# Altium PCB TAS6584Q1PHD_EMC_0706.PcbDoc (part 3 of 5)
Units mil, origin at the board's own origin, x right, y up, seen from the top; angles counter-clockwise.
Board outline 7086.61 x 5118.11 mil, 6 copper layers (Top Layer, GND02, SIG03, SIG04, GND05, Bottom Layer), stack 60.484 mil thick; 461 components, 247 nets, 1337 pads, 1658 vias.
Unrouted connection lines stored in the file: 67.
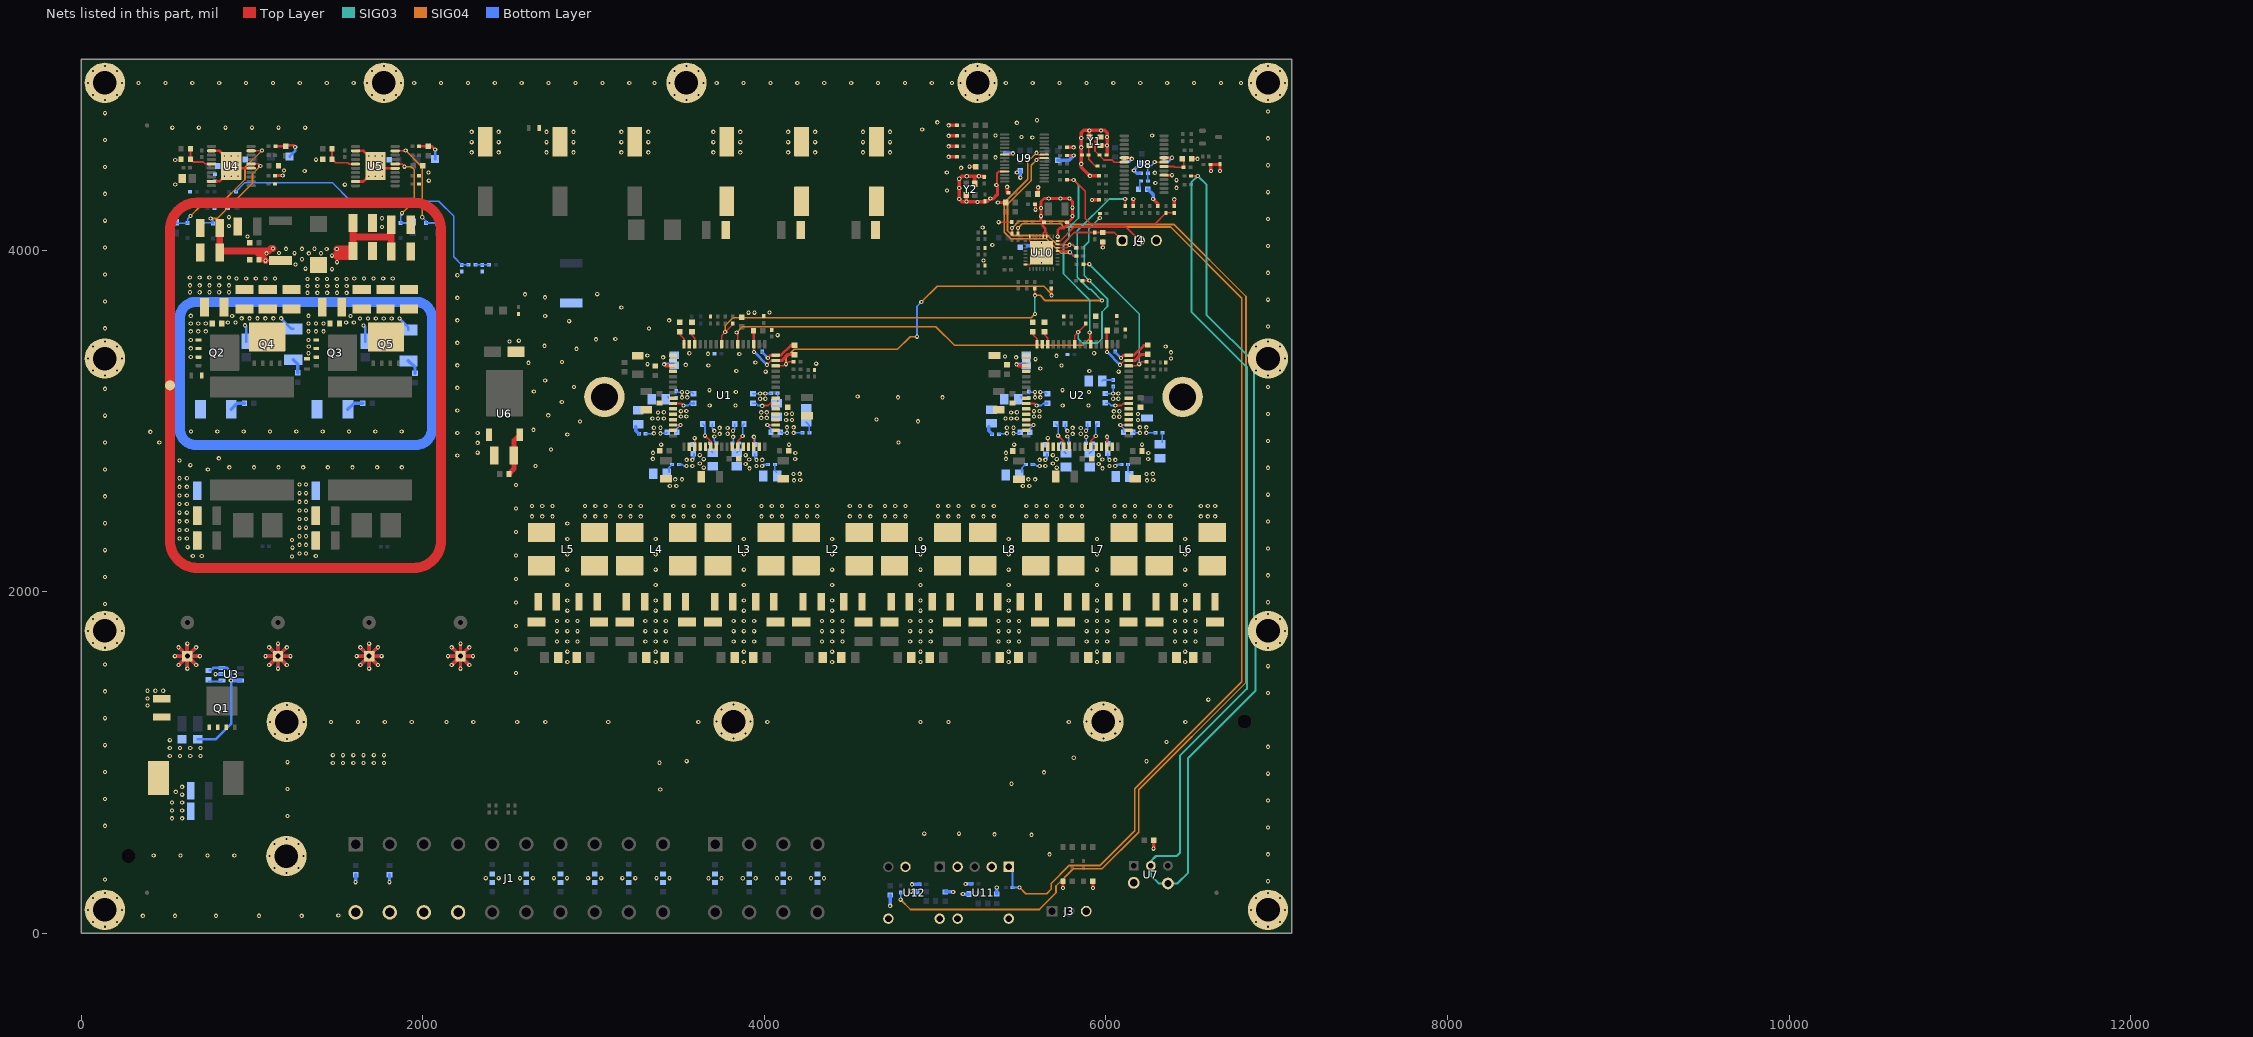
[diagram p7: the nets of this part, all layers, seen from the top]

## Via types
v1: diameter 25, hole 12, Top Layer to Bottom Layer, 1387 vias
v2: diameter 25, hole 12, Top Layer to Bottom Layer, tented both sides, 242 vias
v3: diameter 19.68, hole 7.87, Top Layer to Bottom Layer, 29 vias

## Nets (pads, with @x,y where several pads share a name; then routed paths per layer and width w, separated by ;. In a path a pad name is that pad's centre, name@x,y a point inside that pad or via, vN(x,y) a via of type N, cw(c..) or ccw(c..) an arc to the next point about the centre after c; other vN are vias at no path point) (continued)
GND: C1.2 C2.2 C3.2 C4.2 C5.2 C6.2 C7.2 C8.2 C9.2 C10.1 C11.1 C12.2 C15.2 C16.2 C17.2 C18.2 C35.2 C36.2 C37.2 C38.2 C39.2 C40.2 C41.2 C42.2 C43.2 C44.2 C45.2 C46.2 C47.2 C48.2 C49.2 C50.2 C51.2 C52.2 C53.2 C54.2 C55.2 C56.2 C57.2 C58.2 C59.2 C60.2 C61.2 C62.2 C63.2 C64.2 C65.2 C66.2 C67.2 C68.1 C69.1 C70.2 C73.2 C74.2 C75.2 C76.2 C93.2 C94.2 C95.2 C96.2 C97.2 C98.2 C99.2 C100.2 C101.2 C102.2 C103.2 C104.2 C105.2 C106.2 C107.2 C108.2 C109.2 C110.2 C111.2 C112.2 C113.2 C114.2 C115.2 C116.2 C117.2 C119.2 C121.2 C122.2 C123.2 C124.2 C125.1 C126.2 C128.2 C129.1 C131.1 C133.1 C134.2 C135.1 C136.1 C137.2 C138.2 C139.2 C140.2 C141.2 C143.2 C145.2 C146.2 C147.2 C148.2 C149.2 C150.2 C151.2 C152.2 C153.2 C158.2 C159.2 C160.2 C161.2 C162.2 C163.2 C164.2 C165.2 C166.2 C167.2 C168.2 C169.1 C170.1 C171.1 C172.1 C173.1 C174.1 C175.1 C176.2 C177.2 C178.2 C179.1 C180.2 C181.2 C182.1 C183.2 C184.2 C185.2 C186.2 C187.2 C188.2 C189.2 C190.2 C191.2 C192.2 C193.2 C194.2 C199.1 C200.1 C201.1 C202.2 C203.2 C204.2 C205.1 C206.2 C207.1 C208.2 C209.1 C210.2 C211.2 C212.1 C213.1 C214.2 C215.2 C216.1 C217.1 C218.2 C219.2 C220.2 C221.2 C222.2 C223.2 C224.2 C225.2 C226.2 C227.2 C228.1 C229.1 C230.1 D13.2 H1.1 H1.2 J1.2 J1.4 J1.6 J1.8 J3.3 J4.3 MP1.1 MP2.1 pad.2 pad.3 pad.6@620.79,1623.36 pad.6@1151.41,1623.36 pad.6@1685.2,1623.36 pad.6@2220.3,1623.36 Q2.1 Q2.2 Q2.3 Q3.1 Q3.2 Q3.3 R9.2 R11.2 R13.1 R14.2 R15.2 R16.2 R17.2 R18.2 R19.2 R20.2 R21.2 R22.2 R23.2 R34.2 R38.2 R40.2 R42.1 R43.2 R44.2 R45.2 R46.2 R47.2 R48.2 R49.2 R50.2 R51.2 R63.1 R67.1 R70.1 R73.1 R74.1 R80.1 R82.1 R86.1 R93.1 R94.1 R102.2 R108.2 R109.2 R124.2 R127.1 R132.1 R133.1 R134.1 R135.1 R136.1 R137.1 R156.1 RT1.1 RT2.1 RT3.1 U1.15 U1.17 U1.18 U1.20 U1.27 U1.28 U1.29 U1.36 U1.37 U1.44 U1.45 U1.52 U1.53 U1.54 U2.15 U2.17 U2.18 U2.20 U2.27 U2.28 U2.29 U2.36 U2.37 U2.44 U2.45 U2.52 U2.53 U2.54 U3.2 U4.2 U4.9 U4.15 U4.21 U5.2 U5.9 U5.15 U5.21 U6.1 U7.2 U7.4 U7.5 U8.6 U8.19 U8.23 U9.7 U9.12 U10.8 U10.27 U10.28 U10.32 U10.33 U11.2 U11.4 U11.5 U11.8 U12.3 U12.5 U12.8 Y1.2 Y1.4 Y2.2 Y2.4 | length 19128.9
  Top Layer w10: v1(5371.59,4165) D13.2@5449.15,4165 ; U10.8@5528.22,3916.85 5553.81,3916.85 v3(5622.71,3985.75) 5553.81,4054.65 U10.32@5553.81,4080.24 ; U10.28@5632.55,4080.24 5632.55,4100.55 5644,4112 5652.24,4103.76 U10.27@5652.24,4080.24
  Top Layer w11: 5371.62,4461.26 U9.12@5406.61,4461.26 ; U9.7@5406.61,4559.69 5446.69,4559.69 v1(5455,4568)
  Top Layer w12: v1(5358,4382) 5362.36,4386.36 5362.36,4452 5371.62,4461.26 ; Y1.2@5967.48,4613.89 v1(6006.49,4613.89) ; C178.2@6502.24,4435.2 v1(6537.59,4435.2)
  Top Layer w16: U4.9@761.89,4403.81 808.15,4403.81 v3(838.66,4434.33) ; U4.2@761.89,4582.95 808.15,4582.95 v3(838.66,4552.44) ; v3(917.4,4473.7) 924.29,4480.59 U4.15@994.17,4480.59 ; R67.1@1134.49,4437.38 1134.62,4437.51 1178.47,4437.51 v1(1178.6,4437.64) ; U5.9@1605.51,4403.42 1651.77,4403.42 v3(1682.28,4433.93) ; U5.2@1605.51,4582.55 1651.77,4582.55 v3(1682.28,4552.04) ; v3(1761.02,4473.3) 1767.91,4480.19 U5.15@1837.8,4480.19 ; v1(5201.2,4490) C203.2@5237.44,4490 ; 5644,4112 5644,4127.73 5630.31,4141.42 5630.31,4165 5620,4175.31 v1(5620,4200) v1(5620,4247.91) 5620,4286 5637,4303 v1(5665,4303) v1(5734,4303) v1(5787,4303) 5804,4286 v1(5804,4249.5) v1(5804,4201) 5804,4189.04 5779.96,4165 5779.96,4155.96 5754.5,4130.5 5731.62,4130.5 5717,4115.88 v1(5717,4080) ; v1(5748.38,265.73) C189.2@5748.38,305.75 ; v1(5923.62,265.04) C187.2@5923.62,305.05 ; U8.6@6107.72,4541.97 6145.17,4541.97 v1(6151.55,4535.59) ; U8.19@6340,4439.61 v1(6387.03,4439.61) ; U8.23@6340,4541.97 v1(6387.03,4541.97) ; C181.2@6502.24,4535.59 v1(6536.59,4535.59)
  Top Layer w20: v1(547.64,1623.36) pad.6@620.79,1623.36 ; v1(569.07,1571.64) pad.6@620.79,1623.36 ; v1(569.07,1675.09) pad.6@620.79,1623.36 ; v1(620.79,1550.22) pad.6@620.79,1623.36 ; v1(620.79,1696.51) pad.6@620.79,1623.36 ; v1(672.52,1571.64) pad.6@620.79,1623.36 ; v1(672.52,1675.09) pad.6@620.79,1623.36 ; v1(693.94,1623.36) pad.6@620.79,1623.36 ; v1(1078.26,1623.36) pad.6@1151.41,1623.36 ; v1(1099.68,1571.64) pad.6@1151.41,1623.36 ; v1(1099.68,1675.09) pad.6@1151.41,1623.36 ; v1(1151.41,1550.22) pad.6@1151.41,1623.36 ; v1(1151.41,1696.51) pad.6@1151.41,1623.36 ; v1(1203.13,1571.64) pad.6@1151.41,1623.36 ; v1(1203.13,1675.09) pad.6@1151.41,1623.36 ; v1(1224.56,1623.36) pad.6@1151.41,1623.36 ; v1(1612.05,1623.36) pad.6@1685.2,1623.36 ; v1(1633.47,1571.64) pad.6@1685.2,1623.36 ; v1(1633.47,1675.09) pad.6@1685.2,1623.36 ; v1(1685.2,1550.22) pad.6@1685.2,1623.36 ; v1(1685.2,1696.51) pad.6@1685.2,1623.36 ; v1(1736.92,1571.64) pad.6@1685.2,1623.36 ; v1(1736.92,1675.09) pad.6@1685.2,1623.36 ; v1(1758.34,1623.36) pad.6@1685.2,1623.36 ; v1(2147.15,1623.36) pad.6@2220.3,1623.36 ; v1(2168.57,1571.64) pad.6@2220.3,1623.36 ; v1(2168.57,1675.09) pad.6@2220.3,1623.36 ; v1(2220.3,1550.22) pad.6@2220.3,1623.36 ; v1(2220.3,1696.51) pad.6@2220.3,1623.36 ; v1(2272.02,1571.64) pad.6@2220.3,1623.36 ; v1(2272.02,1675.09) pad.6@2220.3,1623.36 ; v1(2293.45,1623.36) pad.6@2220.3,1623.36 ; v1(5079.07,4547.07) R133.1@5126.67,4547.07 ; v1(5079.07,4608.53) R135.1@5126.67,4608.53 ; v1(5079.07,4670) R134.1@5126.67,4670 ; v1(5079.07,4731.47) R132.1@5126.67,4731.47 ; Y2.2@5182.95,4324.72 v1(5182.95,4285.05) ; Y2.4@5232.16,4389.68 5232.16,4432.75 5233,4433.59 ; C199.1@5291.78,4433.59 v1(5255.59,4433.59) 5233,4433.59 ; v1(5358,4382) 5364.84,4375.16 5364.84,4328.12 5339.56,4302.85 v1(5322.85,4302.85) 5307.28,4287.28 C200.1@5291.78,4287.28 5287.84,4283.35 v1(5248.35,4283.35) 5184.65,4283.35 v1(5182.95,4285.05) ; v1(5367,4280) C204.2@5405.9,4280 ; C205.1@5421.65,4337.09 v1(5421.65,4371.65) ; v1(5587.24,4237.76) C201.1@5587.24,4270 ; C202.2@5602.99,4330 v1(5602.99,4368.99) ; R136.1@5774.64,4555.24 v1(5811,4555.24) ; R137.1@5774.64,4602.95 v1(5811,4602.95) ; Y1.4@5902.52,4663.11 v1(5902.52,4702) ; v1(5918,4295) R109.2@5956.38,4295 ; R108.2@5956.38,4436.19 v1(5905.42,4436.19) 5855.28,4486.33 v1(5855.28,4506.33) v1(5855.28,4603) v1(5855.28,4658) 5855.28,4687.28 5870,4702 v1(5902.52,4702) ; v1(5981.55,4016.33) C218.2@5981.55,4056.76 ; C177.2@6006.49,4558 v1(6006.49,4613.89) v1(6006.49,4663.09) 6006.49,4688.01 5992.5,4702 v1(5971,4702) v1(5902.52,4702) ; C188.2@6160.51,4262.4 v1(6160.51,4300.49) ; v1(6276.73,4300) 6304.08,4272.64 C185.2@6304.08,4262.4 ; v1(6279.02,496.1) C175.1@6279.02,545 ; C186.2@6399.8,4262.4 v1(6399.8,4298.55) ; v1(6614.74,4464) 6614.74,4502.45 6668,4502.45 v1(6668,4464) ; v1(5182.95,4285.05) 5155.95,4285.05 v1(5141,4300) v1(5141,4365) v1(5141,4419) 5155.59,4433.59 v1(5184.65,4433.59) 5233,4433.59
  SIG03 w12: v1@6876,1700.89 6876,1421.91 6481,1026.91 6481,354.42 6418.9,292.31 U7.5@6362.9,292.31 6308.28,292.31 6262.9,337.69 U7.2@6262.9,395.86 6262.9,422.9 6292.8,452.8 6415.02,452.8 6432.63,470.41 6432.63,1039.63 6824.98,1431.98 6824.98,3315.02 6500,3640 6500,4397.61 v1(6537.59,4435.2) 6590,4382.78 6590,3620.49 6876,3334.49 v1@6876,3296.07 ; v1(6878.74,1700.89) 6866.83,1712.8 6866.83,1829.13 v1(6878.74,1841.04) 6866.91,1852.88 6866.91,3284.23 v1(6878.74,3296.07)
  Bottom Layer w16: v1(785.18,1517.81) U3.2@823.3,1517.81 ; C182.1@6107.72,4520.31 6136.27,4520.31 v1(6151.55,4535.59) ; C179.1@6340,4520.31 6365.38,4520.31 v1(6387.03,4541.97)
  Bottom Layer w20: v1(547.64,1623.36) pad.6@620.79,1623.36 ; v1(569.07,1571.64) pad.6@620.79,1623.36 ; v1(569.07,1675.09) pad.6@620.79,1623.36 ; v1(620.79,1550.22) pad.6@620.79,1623.36 ; v1(620.79,1696.51) pad.6@620.79,1623.36 ; v1(672.52,1571.64) pad.6@620.79,1623.36 ; v1(672.52,1675.09) pad.6@620.79,1623.36 ; v1(693.94,1623.36) pad.6@620.79,1623.36 ; v1(1078.26,1623.36) pad.6@1151.41,1623.36 ; v1(1099.68,1571.64) pad.6@1151.41,1623.36 ; v1(1099.68,1675.09) pad.6@1151.41,1623.36 ; v1(1151.41,1550.22) pad.6@1151.41,1623.36 ; v1(1151.41,1696.51) pad.6@1151.41,1623.36 ; v1(1203.13,1571.64) pad.6@1151.41,1623.36 ; v1(1203.13,1675.09) pad.6@1151.41,1623.36 ; v1(1224.56,1623.36) pad.6@1151.41,1623.36 ; v1(1606,299.56) C121.2@1606,342.44 ; v1(1612.05,1623.36) pad.6@1685.2,1623.36 ; v1(1633.47,1571.64) pad.6@1685.2,1623.36 ; v1(1633.47,1675.09) pad.6@1685.2,1623.36 ; v1(1685.2,1550.22) pad.6@1685.2,1623.36 ; v1(1685.2,1696.51) pad.6@1685.2,1623.36 ; v1(1736.92,1571.64) pad.6@1685.2,1623.36 ; v1(1736.92,1675.09) pad.6@1685.2,1623.36 ; v1(1758.34,1623.36) pad.6@1685.2,1623.36 ; v1(1804.28,299.56) C122.2@1804.28,342.44 ; v1(2147.15,1623.36) pad.6@2220.3,1623.36 ; v1(2168.57,1571.64) pad.6@2220.3,1623.36 ; v1(2168.57,1675.09) pad.6@2220.3,1623.36 ; v1(2220.3,1550.22) pad.6@2220.3,1623.36 ; v1(2220.3,1696.51) pad.6@2220.3,1623.36 ; v1(2272.02,1571.64) pad.6@2220.3,1623.36 ; v1(2272.02,1675.09) pad.6@2220.3,1623.36 ; v1(2293.45,1623.36) pad.6@2220.3,1623.36 ; v1(4736.22,161.36) R156.1@4736.22,224.53 ; v1(4858.4,244.19) C211.2@4892.45,244.19 ; v1(4864.01,287.19) C213.1@4908.19,287.19 ; C215.2@5059.2,242.56 v1(5105.37,242.56) ; v1(5161.72,230) C210.2@5197.61,230 ; v1(5178.71,289.5) C212.1@5213.36,289.5 ; C214.2@5360.46,230.35 v1(5360.46,268.29) ; C207.1@5406.61,4567.56 5454.56,4567.56 v1(5455,4568) ; v1(5498.58,4425.46) C206.2@5498.58,4466.67 ; 5539.13,4025.71 5604.6,4025.71 v3(5622.71,4043.82) ; C194.2@5717,4527.68 5717.12,4527.8 5783.56,4527.8 v1(5811,4555.24) ; C183.2@6198.27,4451.42 6179.55,4451.42 v1(6163.15,4467.81) 6201.28,4505.94 C176.2@6210,4505.94 ; C184.2@6245.51,4358.01 6276.73,4326.8 v1(6276.73,4300)
  other v1: 137.8,38.69 6948.82,38.69 67.72,67.72 207.87,67.72 6878.74,67.72 7018.89,67.72 360,102.9 548.96,102.9 787.92,102.9 1040.93,102.9 1290.01,102.9 1505,105 38.69,137.8 236.9,137.8 6849.72,137.8 7047.92,137.8 67.72,207.87 207.87,207.87 6878.74,207.87 7018.89,207.87 137.8,236.9 6948.82,236.9 2368,323 2444,323 2568,323 2644,323 2768,323 2844,323 2968,323 3044,323 3168,323 3244,323 3368,323 3444,323 3673,322.65 3749,322.65 3873,322.65 3949,322.65 4073,322.65 4149,322.65 4273,322.65 4349,322.65 1200.79,353.65 1130.71,382.68 1270.86,382.68 1101.69,452.76 1299.89,452.76 1130.71,522.83 1270.86,522.83 1200.79,551.86 5563.41,576.91 5347.67,579.8 4935.9,584.1 5138.91,584.1 530.47,673.87 590.47,673.87 530.47,720 590.47,720 530.47,766.13 590.47,766.13 590.47,812.4 552.85,828.7 3389.86,842.3 590.47,858.02 5446.16,876.01 5636.56,943.17 1472.76,997.56 1532.76,997.56 1592.76,997.56 1652.76,997.56 1712.76,997.56 1772.76,997.56 3386,999 6238,1008.02 3544.96,1008.33 5811.32,1028.38 1472.76,1043.69 1532.76,1043.69 1592.76,1043.69 1652.76,1043.69 1712.76,1043.69 1772.76,1043.69 6355.14,1120 1203.18,1138.67 3818.9,1140.9 5984.25,1141.06 1133.1,1167.69 1273.25,1167.69 3748.82,1169.92 3888.97,1169.92 5914.18,1170.08 6054.33,1170.08 3085.44,1237.12 3612.71,1237.12 4016.98,1237.12 4913.94,1237.12 5077.78,1237.12 5782.49,1237.12 6464.52,1237.12 1104.07,1237.77 1302.28,1237.77 2717.04,1237.77 3719.8,1240 3918,1240 5885.15,1240.16 6083.35,1240.16 1133.1,1307.85 1273.25,1307.85 3748.82,1310.08 3888.97,1310.08 5914.18,1310.23 6054.33,1310.23 388,1335 1203.18,1336.87 3818.9,1339.1 5984.25,1339.26 388,1375 386.76,1420.82 432.9,1420.82 479.03,1420.82 2545.31,1524.09 2845.97,1589.59 3362.83,1589.59 3879.69,1589.59 4396.55,1589.59 4913.42,1589.59 5430.28,1589.59 5947.14,1589.59 6464,1589.59 2845.97,1649.59 3362.83,1649.59 3879.69,1649.59 4396.55,1649.59 4913.42,1649.59 5430.28,1649.59 5947.14,1649.59 6464,1649.59 2545.31,1661.86 6948.82,1671.87 137.8,1672.55 7018.89,1700.89 67.72,1701.58 207.87,1701.58 2785.97,1709.59 2845.97,1709.59 2905.97,1709.59 3302.83,1709.59 3362.83,1709.59 3422.83,1709.59 3819.69,1709.59 3879.69,1709.59 3939.69,1709.59 4336.55,1709.59 4396.55,1709.59 4456.55,1709.59 4853.42,1709.59 4913.42,1709.59 4973.42,1709.59 5370.28,1709.59 5430.28,1709.59 5490.28,1709.59 5887.14,1709.59 5947.14,1709.59 6007.14,1709.59 6404,1709.59 6464,1709.59 6524,1709.59 2785.97,1769.59 2845.97,1769.59 2905.97,1769.59 3302.83,1769.59 3362.83,1769.59 3422.83,1769.59 3819.69,1769.59 3879.69,1769.59 3939.69,1769.59 4336.55,1769.59 4396.55,1769.59 4456.55,1769.59 4853.42,1769.59 4913.42,1769.59 4973.42,1769.59 5370.28,1769.59 5430.28,1769.59 5490.28,1769.59 5887.14,1769.59 5947.14,1769.59 6007.14,1769.59 6404,1769.59 6464,1769.59 6524,1769.59 7047.92,1770.97 38.69,1771.65 236.9,1771.65 2545.31,1799.63 2785.97,1829.59 2845.97,1829.59 2905.97,1829.59 3302.83,1829.59 3362.83,1829.59 3422.83,1829.59 3819.69,1829.59 3879.69,1829.59 3939.69,1829.59 4336.55,1829.59 4396.55,1829.59 4456.55,1829.59 4853.42,1829.59 4913.42,1829.59 4973.42,1829.59 5370.28,1829.59 5430.28,1829.59 5490.28,1829.59 5887.14,1829.59 5947.14,1829.59 6007.14,1829.59 6404,1829.59 6464,1829.59 6524,1829.59 7018.89,1841.04 67.72,1841.73 207.87,1841.73 6948.82,1870.07 137.8,1870.76 2845.97,1889.59 3362.83,1889.59 3879.69,1889.59 4396.55,1889.59 4913.42,1889.59 5430.28,1889.59 5947.14,1889.59 6464,1889.59 2545.31,1937.4 2845.97,1949.59 3362.83,1949.59 3879.69,1949.59 4396.55,1949.59 4913.42,1949.59 5430.28,1949.59 5947.14,1949.59 6464,1949.59 2845.97,2039.59 3362.83,2039.59 3879.69,2039.59 4396.55,2039.59 4913.42,2039.59 5430.28,2039.59 5947.14,2039.59 6464,2039.59 2545.31,2075.17 2845.97,2129.59 3362.83,2129.59 3879.69,2129.59 4396.55,2129.59 4913.42,2129.59 5430.28,2129.59 5947.14,2129.59 6464,2129.59 1233.88,2206.7 652.99,2209.67 704.9,2209.67 1372.91,2209.67 2545.31,2212.94 2845.97,2219.59 3362.83,2219.59 3879.69,2219.59 4396.55,2219.59 4913.42,2219.59 5430.28,2219.59 5947.14,2219.59 6464,2219.59 1277.62,2225 1315,2225 1236.78,2258.35 622.63,2261.53 1277.62,2275 1315,2275 1233.21,2303.19 2845.97,2309.59 3362.83,2309.59 3879.69,2309.59 4396.55,2309.59 4913.42,2309.59 5430.28,2309.59 5947.14,2309.59 6464,2309.59 575.25,2311.97 617.63,2311.97 1277.62,2325.43 1315,2325.43 2545.31,2350.71 575.25,2362.4 617.63,2362.4 1277.62,2375.87 1315,2375.87 2845.97,2399.59 575.25,2412.83 617.63,2412.83 1277.62,2426.3 1315,2426.3 575.25,2463.27 617.63,2463.27 1277.62,2476.73 1315,2476.73 2545.31,2488.47 575.25,2513.7 617.63,2513.7 1277.62,2527.17 1315,2527.17 575.25,2564.13 617.63,2564.13 1277.62,2577.6 1315,2577.6 575.25,2614.57 617.63,2614.57 2545.31,2626.24 1277.62,2628.03 1315,2628.03 575.25,2665 617.63,2665 740.57,2716.54 866.26,2729.16 1010.58,2729.16 1154.91,2729.16 1299.24,2729.16 1443.56,2729.16 1587.89,2729.16 1732.21,2729.16 1876.54,2729.16 2660.05,2736.5 638,2742 575.25,2769.42 804.84,2781.66 2201.82,2798.66 2320.63,2814.97 2750.64,2833.4 2320.55,2872.72 456.3,2874.02 4785.18,2874.63 2846,2921.73 2320.55,2929.92 2201.82,2930.54 404,2937.1 642,2939 796.18,2939 950.37,2939 1104.55,2939 1258.74,2939 1412.92,2939 1567.11,2939 1721.29,2939 1875.48,2939 2647.63,2948.41 5419.46,2960.8 4171.27,2963.48 2919.54,2997.36 4899.93,2998.57 4656.25,3009.13 2734.15,3033.4 2201.82,3062.43 3679.09,3090.98 3830.74,3090.98 5746.45,3090.98 5898.09,3090.98 2813.4,3111.05 4782.43,3138.8 5043.22,3138.8 4546.06,3143.27 3832.82,3169.8 5900.18,3169.8 2649.46,3172.45 3678.39,3180.95 5745.74,3180.95 2201.82,3194.31 2884.28,3199.22 2715.98,3237 137.8,3267.04 6948.82,3267.04 3835.21,3292.75 5902.57,3292.75 67.72,3296.07 207.87,3296.07 7018.89,3296.07 5615.33,3308.26 3671.65,3324.98 5739,3324.98 2201.82,3326.19 3539.2,3329.46 3315.67,3333.22 4303.29,3336.05 2619.04,3341.14 3946.99,3342.9 2815.21,3345.97 5587.44,3362.37 38.69,3366.14 236.9,3366.14 6380.98,3366.89 7047.92,3366.14 3406.8,3373.43 5474.15,3373.43 640.71,3375.74 5408.73,3377.9 5710.59,3381.91 3314.55,3383.86 3852.84,3392.47 3670.17,3393.71 1330.61,3397.01 5931.17,3396.98 3560.41,3397.15 6380.98,3402.71 2899.91,3422.89 640.71,3425.63 67.72,3436.22 207.87,3436.22 6349.76,3436.22 6878.74,3436.22 7018.89,3436.22 1331.52,3437.29 2712.34,3440.35 2201.82,3458.07 137.8,3465.24 2506.97,3466.07 6948.82,3465.24 2561.73,3471.06 640.71,3475.14 1330.66,3475.14 3013.32,3478.42 3126.88,3480.54 4077.79,3503.04 640.71,3525.31 684.56,3525.31 728.4,3525.31 1330.66,3525.31 1374.5,3525.31 1418.35,3525.31 3324.13,3541.69 640.71,3571.29 684.56,3571.29 728.4,3571.29 1330.66,3571.29 1374.5,3571.29 1418.35,3571.29 2856.71,3584.86 2201.82,3589.96 3442.17,3589.67 2715.98,3614.74 640.71,3616.13 1330.66,3616.13 3906.38,3634.91 3941.9,3634.64 4029.82,3635.62 3162.2,3664.53 2201.82,3721.84 2714.53,3724.4 2597.84,3741.82 3020.96,3743.09 1324.94,3751.17 1382.08,3751.17 1439.23,3751.17 1496.37,3751.17 1553.52,3751.17 635.85,3754.17 692.99,3754.17 750.14,3754.17 807.28,3754.17 864.43,3754.17 1324.94,3790.91 1382.08,3790.91 1439.23,3790.91 1496.37,3790.91 1553.52,3790.91 635.85,3794.91 692.99,3794.91 750.14,3794.91 807.28,3794.91 864.43,3794.91 1324.51,3832 1381.66,3832 1438.8,3832 1495.95,3832 1553.09,3832 909.1,3835 965.46,3835 1021.82,3835 1078.18,3835 1134.54,3835 1598.19,3835 1654.55,3835 1710.91,3835 1767.27,3835 1823.63,3835 635.42,3841 692.57,3841 749.71,3841 806.86,3841 864,3841 2201.82,3853.72 5282.96,3940.42 5334.86,4030.86 972.43,4081.02 5277.71,4132.91 1760.3,4136.06 865.09,4142.78 1760.3,4187.62 864.43,4193.66 5069.8,4349.86 6412.81,4365.68 1542.66,4384.31 549.76,4385.58 6288.96,4394.72 2034.7,4407.82 6412.81,4410.35 6285.94,4453.74 2032.57,4454.93 5067.87,4456.03 5477.91,4455.8 1307.87,4463.71 1186.86,4467.4 5151.81,4482.84 549.76,4528.79 1374.5,4530.69 5353.56,4544.55 2285.56,4573.43 2443.56,4573.43 2723.91,4573.43 2881.91,4573.43 3162.2,4573.43 3320.2,4573.43 3700.54,4573.43 3858.54,4573.43 4138.88,4573.43 4296.88,4573.43 4577.22,4573.43 4735.22,4573.43 2285.56,4633.43 2443.56,4633.43 2723.91,4633.43 2881.91,4633.43 3162.2,4633.43 3320.2,4633.43 3700.54,4633.43 3858.54,4633.43 4138.88,4633.43 4296.88,4633.43 4577.22,4633.43 4735.22,4633.43 5568.7,4660.58 5505.72,4663.11 5352.65,4672.86 6270.74,4672.86 2285.56,4693.43 2443.56,4693.43 2723.91,4693.43 2881.91,4693.43 3162.2,4693.43 3320.2,4693.43 3700.54,4693.43 3858.54,4693.43 4138.88,4693.43 4296.88,4693.43 4577.22,4693.43 4735.22,4693.43 4923.48,4708 532.52,4718.22 688.11,4718.22 843.69,4718.22 999.28,4718.22 1154.87,4718.22 1310.45,4718.22 5477.84,4746.64 5012.29,4749.6 5596.64,4761.5 137.8,4881.21 1771.65,4881.21 3543.31,4881.21 5248.03,4881.21 6948.82,4881.21 67.72,4910.24 207.87,4910.24 1701.58,4910.24 1841.73,4910.24 3473.23,4910.24 3613.38,4910.24 5177.96,4910.24 5318.11,4910.24 6878.74,4910.24 7018.89,4910.24 38.69,4980.31 236.9,4980.31 1672.55,4980.31 1870.76,4980.31 3444.2,4980.31 3642.41,4980.31 5148.93,4980.31 5347.13,4980.31 6849.72,4980.31 7047.92,4980.31 67.72,5050.39 207.87,5050.39 1701.58,5050.39 1841.73,5050.39 3473.23,5050.39 3613.38,5050.39 5177.96,5050.39 5318.11,5050.39 6878.74,5050.39 7018.89,5050.39 137.8,5079.42 1771.65,5079.42 3543.31,5079.42 5248.03,5079.42 6948.82,5079.42
  other v2: 6948.82,305.12 137.8,314.96 423.62,455.79 581.1,455.79 738.58,455.79 896.06,455.79 5670,463 6948.82,462.6 6948.82,620.08 137.8,629.92 1207.8,687.8 6948.82,777.56 137.8,787.4 1207.8,845.28 6948.82,935.04 137.8,944.88 1207.8,1002.76 6948.82,1092.52 137.8,1102.36 1462.38,1237.77 1619.86,1237.77 1777.34,1237.77 1934.82,1237.77 2137.65,1237.77 2295.13,1237.77 2551.8,1237.77 137.8,1259.84 6599.62,1368.38 6948.82,1407.48 137.8,1417.32 6948.82,1564.96 137.8,1574.8 137.8,1929.13 6948.82,1938.98 137.8,2086.61 6948.82,2096.46 137.8,2244.09 6948.82,2253.94 137.8,2401.57 6948.82,2411.42 137.8,2559.06 6948.82,2568.9 3445.99,2619.89 3484.08,2619.89 5513.34,2619.89 5551.44,2619.89 4173.11,2653.11 6240.47,2653.11 4209.24,2655.02 6276.6,2655.02 3477.89,2658.63 3517.92,2658.63 5545.25,2658.63 5585.27,2658.63 4170.65,2689.58 6238,2689.58 4206.65,2690.98 6274,2690.98 137.8,2716.54 3912.16,2723.17 5979.51,2723.17 6948.82,2726.38 3644.59,2727.17 5711.95,2727.17 3889.94,2749.17 5957.29,2749.17 3621.37,2751.17 5688.72,2751.17 3911.16,2775.57 5978.51,2775.57 3644.59,2776.57 5711.95,2776.57 4179.89,2777.93 6247.25,2777.93 3346.63,2778.93 5413.99,2778.93 3621.37,2800.57 3889.94,2800.57 5688.72,2800.57 5957.29,2800.57 4180.77,2812.67 6248.13,2812.67 3347.51,2813.67 5414.87,2813.67 3395.3,2861.88 4144.09,2861.88 5462.65,2861.88 6211.45,2861.88 137.8,2874.02 6948.82,2883.86 4127.64,3006.43 4161.06,3006.43 6186.99,3006.43 3343.83,3015.2 3377.25,3015.2 3410.67,3015.2 5411.18,3015.2 5444.6,3015.2 5478.02,3015.2 3981.48,3019.12 4013.53,3019.12 6046.28,3025.32 6078.33,3025.32 3510.74,3026.43 3542.79,3026.43 5578.1,3026.43 5610.15,3026.43 137.8,3031.5 4127.64,3041.91 6186.99,3041.91 6948.82,3041.34 4161.06,3042.81 3377.25,3050.68 3981.48,3050.94 5444.6,3050.68 3410.67,3051.57 4013.53,3051.24 5478.02,3051.57 6046.28,3057.13 6078.33,3057.43 3510.74,3058.24 3542.79,3058.54 5578.1,3058.24 5610.15,3058.54 137.8,3188.98 6948.82,3198.82 4007,3288.98 6074.36,3288.98 137.8,3543.31 6948.82,3553.15 137.8,3700.79 6948.82,3710.63 137.8,3858.27 6948.82,3868.11 137.8,4015.75 6948.82,4025.59 137.8,4173.23 6948.82,4183.07 137.8,4330.71 6948.82,4340.55 137.8,4488.19 6948.82,4498.03 137.8,4645.67 6948.82,4655.51 137.8,4803.15 6948.82,4812.99 334.65,4980.31 492.13,4980.31 649.61,4980.31 807.09,4980.31 964.57,4980.31 1122.05,4980.31 1279.53,4980.31 1437.01,4980.31 1594.49,4980.31 1948.82,4980.31 2106.3,4980.31 2263.78,4980.31 2421.26,4980.31 2578.74,4980.31 2736.22,4980.31 2893.7,4980.31 3051.18,4980.31 3208.66,4980.31 3356.3,4980.31 3720.47,4980.31 3877.95,4980.31 4035.43,4980.31 4192.91,4980.31 4350.39,4980.31 4507.87,4980.31 4665.35,4980.31 4822.83,4980.31 4980.31,4980.31 5098.43,4980.31 5413.39,4980.31 5570.87,4980.31 5728.35,4980.31 5885.83,4980.31 6043.31,4980.31 6200.79,4980.31 6358.27,4980.31 6515.75,4980.31 6673.23,4980.31 6791.34,4980.31
  other v3: 5622.71,3927.68 5564.64,3985.75 5680.78,3985.75 1721.65,4433.93 1761.02,4433.93 878.03,4434.33 917.4,4434.33 838.66,4473.7 878.03,4473.7 1682.28,4473.3 1721.65,4473.3 838.66,4513.07 878.03,4513.07 917.4,4513.07 1682.28,4512.67 1721.65,4512.67 1761.02,4512.67 1721.65,4552.04 1761.02,4552.04 878.03,4552.44 917.4,4552.44
GPIO_1: R2.1 R126.1 R148.2 U1.9 | length 3449
  Top Layer w10: U1.9@3749.25,3450.2 3749.25,3500.78 v1(3769.98,3521.5) 3814.21,3565.74 R2.1@3814.21,3572.11 ; v1(5583.77,3736.46) R148.2@5583.77,3771.38 ; R126.1@6112.65,4262.4 v1(6112.65,4300.49)
  SIG04 w10: v1(3769.98,3521.5) 3769.98,3559.62 3815.76,3605.4 5562.22,3605.4 v1(5583.77,3626.95) ; v1(5583.77,3736.46) 5614.42,3736.46 5645.38,3705.5 5823.22,3705.5 v1(5977,3705.5)
  SIG03 w10: v1(5583.77,3626.95) v1(5583.77,3736.46) ; v1(5977,3705.5) 5911.31,3771.18 5902.81,3771.18 5831.55,3842.45 5831.55,4113.55 6018.49,4300.49 v1(6112.65,4300.49)
GPIO_3: R7.1 R149.2 U1.62 | length 2047.7
  Top Layer w10: U1.62@4065.2,3323.23 4111.69,3323.23 4121.68,3333.22 v1(4126.91,3333.22) 4140.77,3347.08 R7.1@4171.31,3347.08 ; v1(5680.54,3736.46) R149.2@5680.54,3771.38
  SIG04 w10: v1(4126.91,3333.22) 4126.91,3373.22 4173.66,3419.97 4778.97,3419.97 4853.19,3494.19 v1(4893.5,3494.19) ; v1(4919,3697) 5011,3789 5637,3789 5680.54,3745.46 v1(5680.54,3736.46)
  Bottom Layer w10: v1(4893.5,3494.19) 4893.5,3671.5 v1(4919,3697)
GPIO_4: R32.1 R125.1 R150.2 U2.9 | length 1224.3
  Top Layer w10: U2.9@5816.61,3450.2 5816.61,3500.78 v1(5837.24,3521.41) 5881.57,3565.74 R32.1@5881.57,3572.11 ; R150.2@5867,3822.65 v1(5902.78,3822.65) ; v1(5964.25,4189.05) R125.1@5964.25,4215.16
  SIG03 w10: v1(5837.24,3521.41) 5837.24,3481.89 5862.2,3456.93 5951.19,3456.93 5976.37,3482.11 5976.37,3638.84 6008.52,3671 6008.52,3716.91 v1(5902.78,3822.65) 5873,3852.44 5873,4024 5900,4051 5900,4124.8 v1(5964.25,4189.05)
GPIO_6: R36.1 R151.2 U2.62 | length 857.7
  Top Layer w10: R151.2@5867,3918.44 v1(5902.78,3918.44) ; U2.62@6132.55,3323.23 6179.04,3323.23 6189.04,3333.22 v1(6194.26,3333.22) 6208.13,3347.08 R36.1@6238.67,3347.08
  SIG03 w10: v1(5902.78,3918.44) 6194.26,3626.95 v1(6194.26,3333.22)
HO1: D8.1 R97.1 U4.19 | length 805.5
  Top Layer w10: U4.19@994.17,4582.95 1056.17,4582.95 v1(1057.87,4584.65)
  SIG04 w10: v1(639.13,4200.53) 699.76,4261.16 805.44,4261.16 958.67,4414.39 958.67,4485.45 v1(1057.87,4584.65)
  Bottom Layer w10: R97.1@551.87,4164.41 557.57,4158.71 D8.1@622.29,4158.71 622.29,4183.69 v1(639.13,4200.53)
HO2: D9.1 R98.1 U5.19 | length 609.7
  Top Layer w10: U5.19@1837.8,4582.55 1896.88,4582.55 v1(1898.95,4584.63)
  SIG04 w10: v1(1898.95,4584.63) 1996.3,4487.28 v1(1996.3,4193.6)
  Bottom Layer w10: v1(1996.3,4193.6) 2018.5,4171.4 D9.1@2018.5,4159.93 2083.91,4159.93 R98.1@2089.62,4165.63
LO1: D6.1 R95.1 U4.16 | length 623
  Top Layer w10: U4.16@994.17,4506.18 1035.29,4506.18 v1(1048.24,4493.22)
  SIG04 w10: v1(757.3,4185.9) 795.74,4185.9 1002.07,4392.23 1002.07,4447.05 v1(1048.24,4493.22)
  Bottom Layer w10: R95.1@700.1,4165.86 R95.1@700.1,4161.33 764.75,4161.33 D6.1@770.54,4155.54 770.54,4172.66 v1(757.3,4185.9)
LO2: D7.1 R96.1 U5.16 | length 544.1
  Top Layer w10: U5.16@1837.8,4505.78 1875.95,4505.78 v1(1891.95,4489.78)
  SIG04 w10: v1(1877.59,4217.28) 1948.82,4288.52 1948.82,4473.3 1932.34,4489.78 v1(1891.95,4489.78)
  Bottom Layer w10: v1(1877.59,4217.28) 1869.81,4209.51 D7.1@1869.81,4159.93 1935.22,4159.93 R96.1@1940.92,4165.63
LRCLK: C186.1 R116.2 R140.1 U1.6 U2.6 | length 4177.1
  Top Layer w10: v1(3837.3,3518.75) 3843.74,3512.31 U1.6@3843.74,3450.2 ; R140.1@5774.64,4412.1 v1(5811,4412.1) 5878,4345.1 5878,4186.52 5909.65,4154.87 6287.72,4154.87 R116.2@6351.94,4219.09 C186.1@6399.8,4219.09 ; v1(5904.66,3518.75) 5911.1,3512.31 U2.6@5911.1,3450.2
  SIG04 w10: v1(3837.3,3518.75) 3871.07,3552.52 5003.86,3552.52 5112.76,3443.62 5865.12,3443.62 5904.66,3483.16 v1(5904.66,3518.75)
  SIG03 w10: v1(5811,4412.1) 5839,4384.1 5839,4189 5783,4133 5783,4070 5751,4038 5751,3861.88 5904.66,3708.22 v1(5904.66,3518.75)
MCU_RST: C218.1 J4.1 R161.1 U10.23 | length 423.8
  Top Layer w10: U10.23@5717.2,4034.96 5745.96,4034.96 5815,4104 R161.1@5932,4104 ; R161.1@5933.65,4104 C218.1@5981.55,4104 6049,4104 J4.1@6095,4058
MCU_RXD: R152.2 R155.1 U11.1 | length 5931.7
  Top Layer w10: R152.2@5484.53,4099.32 v1(5484.53,4129.94)
  SIG04 w10: v1(5484.53,4129.94) 5509.52,4154.94 5735.06,4154.94 5753.51,4136.49 6378.51,4136.49 6796,3719 6796,1474 6168.5,846.5 6168.5,600.5 5966,398 5786,398 5680,292 5680,260 5652.8,232.8 5529.93,232.8 v1(5494.19,268.53)
  Bottom Layer w10: U11.1@5452.73,387.45 5452.73,269.06 R155.1@5453.26,268.53 v1(5494.19,268.53)
MCU_SCL: R144.1 R157.1 U9.24 U10.21 | length 1194.2
  Top Layer w10: v1(5593,4571) 5604.31,4559.69 U9.24@5638.9,4559.69 ; U10.21@5717.2,3995.59 5781.08,3995.59 v1(5788.26,3988.41) 5810.34,3966.33 R144.1@5828.7,3966.33
  SIG04 w10: v1(5593,4571) 5542,4520 5542,4416.87 5403.8,4278.67 5403.8,4105.2 5442,4067 5651.72,4067 5736.72,3982 v1@5784,3982
  Bottom Layer w10: v1(5788.26,3988.41) 5810.34,3966.33 R157.1@5823.7,3966.33
MCU_SDA: R145.1 R160.1 U9.23 U10.22 | length 1104.9
  Top Layer w10: v1(5593,4528.69) 5604.31,4540 U9.23@5638.9,4540 ; U10.22@5717.2,4015.28 5769.41,4015.28 v1(5785.87,4031.74) 5788.2,4034.06 5808.35,4034.06 5828.19,4014.22 R145.1@5828.7,4014.22
  SIG04 w10: v1(5593,4528.69) 5562,4497.69 5562,4408.59 5423.17,4269.76 5423.17,4114.11 5450.28,4087 5660,4087 5715.26,4031.74 v1(5785.87,4031.74)
  Bottom Layer w10: v1(5785.87,4031.74) 5806.18,4031.74 R160.1@5823.7,4014.22
MCU_TST: J4.2 U10.24 | length 544.6
  Top Layer w10: U10.24@5717.2,4054.65 5732.65,4054.65 5815,4137 6116,4137 J4.2@6195,4058
MCU_TXD: R153.2 R154.2 | length 6668.5
  Top Layer w10: R153.2@5449.53,4099.32 v1(5449.53,4129.94)
  SIG04 w10: v1(4797.63,197.36) 4854.98,140 5610.19,140 5707.68,237.49 5707.68,277 5808.25,377.58 5976.88,377.58 6192.17,592.86 6192.17,840.83 6820,1468.66 6820,3729 6397.51,4151.49 5772.51,4151.49 5754.06,4169.94 5489.52,4169.94 v1(5449.53,4129.94)
  Bottom Layer w10: v1(4797.63,197.36) R154.2@4797.63,240.28
NetC10_2: C10.2 U1.14 | length 78.9
  Top Layer w10: C10.2@3575.75,3522.44 3575.75,3501.84 3591.77,3485.82 U1.14@3591.77,3450.2
NetC11_2: C11.2 U1.16 | length 84.8
  Top Layer w10: C11.2@3503.33,3522.44 3507.09,3518.68 3507.09,3503.99 3528.78,3482.3 U1.16@3528.78,3450.2
  Top Layer w19.68: U1.16@3528.78,3450.2 U1.16@3528.78,3452.17
NetC12_1: C12.1 U1.19 | length 122.4
  Top Layer w20: v1(3412.8,3332.23) 3421.8,3323.23 U1.19@3464.8,3323.23
  Bottom Layer w20: v1(3412.8,3332.23) 3466.74,3332.23 C12.1@3472.78,3326.19 C12.1@3469.81,3323.23
NetC13_2: C13.2 C14.2 U1.3 U1.63 | length 420.3
  Top Layer w10: U1.3@3938.23,3450.2 3938.23,3404.57 v1(3939,3403.8) ; v1(4015.12,3329.46) 4040.38,3354.72 U1.63@4065.2,3354.72
  Top Layer w15: C13.2@3935.89,3529.32 3938.23,3526.98 U1.3@3938.23,3450.2
  Top Layer w19.68: U1.63@4065.2,3354.72 4102.6,3354.72 4104.57,3356.69 4137.87,3390 C14.2@4176.64,3390
  Bottom Layer w15: v1(3939,3403.8) 3940.78,3403.8 v1(4015.12,3329.46)
NetC14_1: C14.1 R12.1 U1.64 | length 233.6
  Top Layer w15: v1@4022.31,3372 4036.54,3386.22 U1.64@4065.2,3386.22 4097.69,3386.22 4155.25,3443.78 C14.1@4176.23,3443.78
  Bottom Layer w15: R12.1@3987.59,3405.91 3987.59,3401.95 v1(4020.1,3369.44)
NetC19_1: C19.1 C27.2 L2.4 U1.56 | length 76.6
  Bottom Layer w10: C19.1@3932.8,3159.84 3973.63,3159.84 v2(3974.83,3161.04) ; v2(4005.25,3161.04) 4038.4,3161.04 C27.2@4039.05,3161.7
  other v1: 4500,2442.15 4560,2442.15 4620,2442.15 4500,2502.15 4560,2502.15 4620,2502.15
  other v2: 3974.83,3130.61 4005.25,3130.61
NetC19_2: C19.2 U1.55 | length 143
  Top Layer w10: v1@3987.24,3090.98 4022.31,3090.98 4034.09,3102.76 U1.55@4065.2,3102.76
  Bottom Layer w10: C19.2@3932.8,3104.72 3948.94,3104.72 3962.69,3090.98 v1@3987.24,3090.98
  other v1: 3987.24,3088.98
NetC20_1: C20.1 C28.2 L2.1 U1.50 | length 97.7
  Bottom Layer w10: C20.1@4093.56,2938.88 4101.29,2931.15 v1@4133.24,2931.15 ; v2@4169.27,2931.15 4223.23,2931.15 C28.2@4223.82,2930.57
  other v1: 4189.37,2442.15 4249.37,2442.15 4309.37,2442.15 4189.37,2502.15 4249.37,2502.15 4309.37,2502.15 4132.24,2931.15 4132.24,2963.48
  other v2: 4171.27,2931.15
NetC20_2: C20.2 U1.51 | length 100
  Top Layer w10: v1(4017,2976.77) U1.51@4065.2,2976.77
  Bottom Layer w10: v1(4017,2976.77) 4038.44,2955.33 C20.2@4038.44,2933.88
NetC21_1: C21.1 C29.2 L3.4 U1.47 | length 77.3
  Bottom Layer w10: C21.1@3943.44,2807.65 3943.44,2783.61 v2(3953.91,2773.14) ; v1(3987.07,2736.8) 3995.85,2745.57 C29.2@4021.9,2745.57
  other v1: 3983.16,2442.15 4043.16,2442.15 4103.16,2442.15 3983.16,2502.15 4043.16,2502.15 4103.16,2502.15 3953.74,2736.8 3987.24,2773.14
NetC21_2: C21.2 U1.46 | length 104.9
  Top Layer w10: U1.46@3938.23,2849.8 v1(3938.23,2907.68)
  Bottom Layer w10: v1(3938.23,2907.68) 3943.44,2902.47 C21.2@3943.44,2862.77
NetC22_1: C22.1 C30.2 L3.1 U1.42 | length 81.7
  Bottom Layer w10: C30.2@3812.65,2871.39 3817.24,2875.98 v1(3817.24,2907.68) ; v1(3816.24,2943.34) 3825.52,2952.62 C22.1@3825.52,2982.99
  other v1: 3672.53,2442.15 3732.53,2442.15 3792.53,2442.15 3672.53,2502.15 3732.53,2502.15 3792.53,2502.15 3784.96,2925.68 3784.96,2959.37
NetC22_2: C22.2 U1.43 | length 148.5
  Top Layer w10: U1.43@3843.74,2849.8 3843.74,2883.5 v1(3872.8,2912.55)
  Bottom Layer w10: v1(3872.8,2912.55) 3872.8,2975.14 C22.2@3880.64,2982.99
NetC23_1: C23.1 C31.2 L4.4 U1.39 | length 98
  Bottom Layer w10: C23.1@3693.99,2982.99 3693.99,2958.26 v1@3710.57,2941.68 ; v1(3706.57,2908.99) v1@3706.57,2903.99 ; v1@3710.57,2907.99 v1@3706.57,2903.99 ; C31.2@3720.1,2870.43 3706.57,2883.96 v1@3706.57,2903.99
  other v1: 3466.32,2442.15 3526.32,2442.15 3586.32,2442.15 3466.32,2502.15 3526.32,2502.15 3586.32,2502.15 3737.85,2924.99 3706.57,2942.68 3737.85,2960.64
NetC23_2: C23.2 U1.38 | length 153
  Top Layer w10: v1@3652.57,2914.68 v1(3652.57,2914.47) 3686.26,2880.78 U1.38@3686.26,2849.8
  Bottom Layer w10: C23.2@3638.87,2982.99 3652.57,2969.28 v1(3652.57,2914.47)
NetC24_1: C24.1 C32.2 L4.1 U1.34 | length 88.2
  Bottom Layer w10: C32.2@3499.4,2745.57 3517.99,2745.57 3526.76,2736.8 v1(3544.29,2736.8) ; v1@3577.8,2772.14 3587.83,2782.18 C24.1@3587.83,2807.65
  other v1: 3155.69,2442.15 3215.69,2442.15 3275.69,2442.15 3155.69,2502.15 3215.69,2502.15 3275.69,2502.15 3577.62,2736.8 3577.8,2773.14
  other v2: 3544.46,2773.14
NetC24_2: C24.2 U1.35 | length 88.8
  Top Layer w10: U1.35@3591.77,2849.8 v1(3591.77,2899.87)
  Bottom Layer w10: C24.2@3587.83,2862.77 3591.77,2866.71 v1(3591.77,2899.87)
NetC25_1: C25.1 C33.2 L5.4 U1.31 | length 94.1
  Bottom Layer w10: C33.2@3304.35,2925.97 3352.61,2925.97 v1@3355.11,2928.46 ; v2(3391.14,2928.46) 3425.79,2928.46 C25.1@3431.21,2933.88
  other v1: 2949.48,2442.15 3009.48,2442.15 3069.48,2442.15 2949.48,2502.15 3009.48,2502.15 3069.48,2502.15 3352.11,2928.46 3352.11,2960.8 3391.14,2960.8
NetC25_2: C25.2 U1.30 | length 95.2
  Top Layer w10: U1.30@3464.8,2976.77 v2(3508.11,2976.77)
  Bottom Layer w10: C25.2@3486.32,2933.88 3486.32,2954.99 v2(3508.11,2976.77)
NetC26_1: C26.1 C34.2 L5.1 U1.25 | length 82.4
  Bottom Layer w10: C34.2@3483.31,3174.7 3488.77,3169.23 v2(3517.58,3169.23) ; v2@3514.11,3135.33 v2(3517.58,3138.8) ; v2(3548,3169.23) 3575.67,3169.23 C26.1@3585.06,3159.84
  other v1: 2638.85,2442.15 2698.85,2442.15 2758.85,2442.15 2638.85,2502.15 2698.85,2502.15 2758.85,2502.15
  other v2: 3548,3138.8
NetC26_2: C26.2 U1.26 | length 130.8
  Top Layer w10: U1.26@3464.8,3102.76 3514.98,3102.76 v2(3526.76,3090.98)
  Bottom Layer w10: v2(3526.76,3090.98) 3552.89,3090.98 3564.67,3102.76 C26.2@3583.09,3102.76
  Bottom Layer w19.68: C26.2@3583.09,3102.76 C26.2@3585.06,3104.72
NetC27_1: C27.1 R16.1 | length 61.7
  Bottom Layer w10: R16.1@4071.43,3103.96 4077.52,3110.05 C27.1@4077.52,3163.17
NetC28_1: C28.1 R17.1 | length 70.8
  Bottom Layer w10: R17.1@4245.26,2993.93 4263.19,2975.99 C28.1@4263.19,2930.57
NetC29_1: C29.1 R18.1 | length 48.8
  Bottom Layer w10: C29.1@4061.27,2745.57 4061.27,2710.13 R18.1@4070.72,2700.68
NetC30_1: C30.1 R19.1 | length 61.7
  Bottom Layer w10: R19.1@3837.8,2815.57 3852.02,2829.78 C30.1@3852.02,2871.39
NetC31_1: C31.1 R20.1 | length 61.8
  Bottom Layer w10: C31.1@3680.73,2870.43 3680.73,2832.32 R20.1@3697.48,2815.57
NetC32_1: C32.1 R21.1 | length 52.9
  Bottom Layer w10: R21.1@3440.62,2700.68 3440.62,2726.16 C32.1@3460.03,2745.57
NetC33_1: C33.1 R22.1 | length 48.8
  Bottom Layer w20: R22.1@3246.6,2967.14 3246.6,2944.34 C33.1@3264.98,2925.97
NetC34_1: C34.1 R23.1 | length 52
  Bottom Layer w10: R23.1@3434.16,3142.31 3441.15,3135.33 C34.1@3483.31,3135.33
NetC35_1: C35.1 L2.3 R24.1
NetC36_1: C36.1 L2.2 R25.1
NetC37_1: C37.1 L3.3 R26.1
NetC38_1: C38.1 L3.2 R27.1
NetC39_1: C39.1 L4.3 R28.1
NetC40_1: C40.1 L4.2 R29.1
NetC41_1: C41.1 L5.3 R30.1
NetC42_1: C42.1 L5.2 R31.1
NetC68_2: C68.2 U2.14 | length 78.9
  Top Layer w10: C68.2@5643.1,3522.44 5643.1,3501.84 5659.13,3485.82 U2.14@5659.13,3450.2
NetC69_2: C69.2 U2.16 | length 84.8
  Top Layer w10: C69.2@5570.68,3522.44 5574.45,3518.68 5574.45,3503.99 5596.14,3482.3 U2.16@5596.14,3450.2
  Top Layer w19.68: U2.16@5596.14,3450.2 U2.16@5596.14,3452.17
NetC70_1: C70.1 U2.19 | length 122.8
  Top Layer w20: v1(5476.15,3332.23) 5485.15,3323.23 U2.19@5532.16,3323.23
  Bottom Layer w20: v1(5476.15,3332.23) 5525.13,3332.23 C70.1@5532.16,3325.2 ; C70.1@5537.17,3323.23 C70.1@5540.13,3326.19
NetC71_2: C71.2 C72.2 U2.3 U2.63 | length 420.3
  Top Layer w10: U2.3@6005.58,3450.2 6005.58,3404.57 v1(6006.36,3403.8) ; v1(6082.47,3329.46) 6107.74,3354.72 U2.63@6132.55,3354.72
  Top Layer w15: C71.2@6003.24,3529.32 6005.58,3526.98 U2.3@6005.58,3450.2
  Top Layer w19.68: U2.63@6132.55,3354.72 6169.95,3354.72 6171.92,3356.69 6205.23,3390 C72.2@6244,3390
  Bottom Layer w15: v1(6006.36,3403.8) 6008.13,3403.8 v1(6082.47,3329.46)
NetC72_1: C72.1 R41.1 U2.64 | length 233.6
  Top Layer w15: v1@6089.67,3372 6103.89,3386.22 U2.64@6132.55,3386.22 6165.05,3386.22 6222.6,3443.78 C72.1@6243.59,3443.78
  Bottom Layer w15: R41.1@6054.95,3405.91 6054.95,3401.95 v1(6087.46,3369.44)
NetC77_1: C77.1 C85.2 L6.4 U2.56 | length 84.1
  Bottom Layer w10: C77.1@6000.15,3159.84 6040.99,3159.84 v2(6042.19,3161.04) 6042.19,3201.09 C85.2@6041.81,3201.48 ; C85.2@6042.99,3201.78 C85.2@6043.64,3202.44
  other v1: 6555.36,2442.15 6596.36,2442.15 6639.8,2442.15 6555.36,2502.15 6596.36,2502.15 6639.8,2502.15
  other v2: 6042.19,3130.61 6072.61,3130.61 6072.61,3161.04
NetC77_2: C77.2 U2.55 | length 143
  Top Layer w10: v1(6054.6,3090.98) 6089.67,3090.98 6101.45,3102.76 U2.55@6132.55,3102.76
  Bottom Layer w10: C77.2@6000.15,3104.72 6016.3,3104.72 6030.05,3090.98 v1(6054.6,3090.98)
NetC78_1: C78.1 C86.2 L6.1 U2.50 | length 97.7
  Bottom Layer w10: C78.1@6160.92,2938.88 6168.64,2931.15 v1@6200.6,2931.15 ; v2(6236.63,2931.15) 6290.59,2931.15 C86.2@6291.17,2930.57
  other v1: 6256.73,2442.15 6316.73,2442.15 6376.73,2442.15 6256.73,2502.15 6316.73,2502.15 6376.73,2502.15 6198.6,2931.15 6198.6,2963.48 6236.63,2963.48
NetC78_2: C78.2 U2.51 | length 100
  Top Layer w10: v1(6084.36,2976.77) U2.51@6132.55,2976.77
  Bottom Layer w10: v1(6084.36,2976.77) 6105.8,2955.33 C78.2@6105.8,2933.88
NetC79_1: C79.1 C87.2 L7.4 U2.47 | length 77.3
  Bottom Layer w10: C79.1@6010.8,2807.65 6010.8,2783.61 v2(6021.27,2773.14) ; v1(6054.43,2736.8) 6063.2,2745.57 C87.2@6089.25,2745.57
  other v1: 6050.52,2442.15 6110.52,2442.15 6170.52,2442.15 6050.52,2502.15 6110.52,2502.15 6170.52,2502.15 6021.1,2736.8 6054.6,2773.14
NetC79_2: C79.2 U2.46 | length 104.9
  Top Layer w10: U2.46@6005.58,2849.8 v1(6005.58,2907.68)
  Bottom Layer w10: v1(6005.58,2907.68) 6010.8,2902.47 C79.2@6010.8,2862.77
NetC80_1: C80.1 C88.2 L7.1 U2.42 | length 81.4
  Bottom Layer w10: v1(5883.6,2943.34) 5892.88,2952.62 C80.1@5892.88,2982.99 ; C88.2@5883.79,2870.1 5884.6,2870.91 v1(5884.6,2907.68)
  other v1: 5739.89,2442.15 5799.89,2442.15 5859.89,2442.15 5739.89,2502.15 5799.89,2502.15 5859.89,2502.15 5852.31,2925.68 5852.31,2959.37
NetC80_2: C80.2 U2.43 | length 148.5
  Top Layer w10: U2.43@5911.1,2849.8 5911.1,2883.5 v1(5940.15,2912.55)
  Bottom Layer w10: v1(5940.15,2912.55) 5940.15,2975.14 C80.2@5948,2982.99
NetC81_1: C81.1 C89.2 L8.4 U2.39 | length 89.2
  Bottom Layer w10: C81.1@5761.35,2982.99 5761.35,2958.26 v1@5777.92,2941.68 ; v1(5773.92,2908.99) 5782.32,2900.59 C89.2@5782.32,2871.4
  other v1: 5533.68,2442.15 5593.68,2442.15 5653.68,2442.15 5533.68,2502.15 5593.68,2502.15 5653.68,2502.15 5805.21,2924.99 5773.92,2942.68 5805.21,2960.64
NetC81_2: C81.2 U2.38 | length 153
  Top Layer w10: v1@5719.93,2914.68 v1(5719.93,2914.47) 5753.62,2880.78 U2.38@5753.62,2849.8
  Bottom Layer w10: C81.2@5706.23,2982.99 5719.93,2969.28 v1(5719.93,2914.47)
NetC82_1: C82.1 C90.2 L8.1 U2.34 | length 88.2
  Bottom Layer w10: C90.2@5566.75,2745.57 5585.34,2745.57 5594.12,2736.8 v1(5611.65,2736.8) ; v1@5645.15,2772.14 5655.19,2782.18 C82.1@5655.19,2807.65
  other v1: 5223.05,2442.15 5283.05,2442.15 5343.05,2442.15 5223.05,2502.15 5283.05,2502.15 5343.05,2502.15 5644.98,2736.8 5645.15,2773.14
  other v2: 5611.82,2773.14
NetC82_2: C82.2 U2.35 | length 88.8
  Top Layer w10: U2.35@5659.13,2849.8 v1(5659.13,2899.87)
  Bottom Layer w10: C82.2@5655.19,2862.77 5659.13,2866.71 v1(5659.13,2899.87)
NetC83_1: C83.1 C91.2 L9.4 U2.31 | length 94.1
  Bottom Layer w10: C91.2@5371.71,2925.97 5419.96,2925.97 v1@5422.46,2928.46 ; v2(5458.5,2928.46) 5493.15,2928.46 C83.1@5498.56,2933.88
  other v1: 5016.84,2442.15 5076.84,2442.15 5136.84,2442.15 5016.84,2502.15 5076.84,2502.15 5136.84,2502.15 5419.46,2928.46 5458.5,2960.8
NetC83_2: C83.2 U2.30 | length 95.2
  Top Layer w10: U2.30@5532.16,2976.77 v2(5575.47,2976.77)
  Bottom Layer w10: C83.2@5553.68,2933.88 5553.68,2954.99 v2(5575.47,2976.77)
NetC84_1: C84.1 C92.2 L9.1 U2.25 | length 77.5
  Bottom Layer w10: C92.2@5550.66,3174.7 5556.13,3169.23 v2(5584.94,3169.23) ; v2(5615.36,3169.23) 5643.03,3169.23 C84.1@5652.41,3159.84
  other v1: 4706.21,2442.15 4766.21,2442.15 4826.21,2442.15 4706.21,2502.15 4766.21,2502.15 4826.21,2502.15
  other v2: 5584.94,3138.8 5615.36,3138.8
NetC84_2: C84.2 U2.26 | length 130.8
  Top Layer w10: U2.26@5532.16,3102.76 5582.34,3102.76 v2(5594.12,3090.98)
  Bottom Layer w10: v2(5594.12,3090.98) 5620.25,3090.98 5632.03,3102.76 C84.2@5650.44,3102.76
  Bottom Layer w19.68: C84.2@5650.44,3102.76 C84.2@5652.41,3104.72
NetC85_1: C85.1 R34.1 | length 65.2
  Bottom Layer w10: R34.1@5978.99,3235.16 5984.68,3240.85 C85.1@6041.81,3240.85
NetC86_1: C86.1 R45.1 | length 55.1
  Bottom Layer w10: R45.1@6328.74,2876.03 6330.12,2877.41 C86.1@6330.12,2930.57
NetC87_1: C87.1 R46.1 | length 48.8
  Bottom Layer w10: C87.1@6128.62,2745.57 6128.62,2710.13 R46.1@6138.08,2700.68
NetC88_1: C88.1 R47.1 | length 67.5
  Bottom Layer w10: R47.1@5902.54,2811.1 5923.16,2831.71 C88.1@5923.16,2870.1
NetC89_1: C89.1 R48.1 | length 69.6
  Bottom Layer w10: C89.1@5742.95,2871.4 5742.95,2833.63 R48.1@5765.48,2811.1
NetC90_1: C90.1 R49.1 | length 52.9
  Bottom Layer w10: R49.1@5507.98,2700.68 5507.98,2726.16 C90.1@5527.38,2745.57
NetC91_1: C91.1 R50.1 | length 48.8
  Bottom Layer w20: R50.1@5313.96,2967.14 5313.96,2944.34 C91.1@5332.34,2925.97
NetC92_1: C92.1 R51.1 | length 52
  Bottom Layer w10: R51.1@5501.52,3142.31 5508.5,3135.33 C92.1@5550.66,3135.33
NetC93_1: C93.1 L6.3 R53.1
NetC94_1: C94.1 L6.2 R54.1
NetC95_1: C95.1 L7.3 R55.1
NetC96_1: C96.1 L7.2 R56.1
NetC97_1: C97.1 L8.3 R57.1
NetC98_1: C98.1 L8.2 R58.1
NetC99_1: C99.1 L9.3 R59.1
NetC100_1: C100.1 L9.2 R60.1
NetC118_2: C118.2 R62.2 | length 79.5
  Bottom Layer w10: R62.2@779.36,4245.77 786.25,4252.66 C118.2@855.99,4252.66
NetC124_1: C124.1 R71.1 U4.5 | length 195.1
  Top Layer w10: R71.1@638.91,4594.44 C124.1@638.91,4533.78 655.14,4517.55 712.6,4517.55 723.98,4506.18 U4.5@761.89,4506.18
NetC125_2: C125.2 R64.2 R72.1 | length 80.7
  Bottom Layer w10: R72.1@2307.65,3915.9 R64.2@2388.39,3915.9
NetC126_1: C126.1 C127.1 D1.2 D2.2 L10.2 Q1.1 Q1.2 Q1.3 U3.3 U3.6 | length 733.5
  Bottom Layer w15: D2.2@681.25,1136.22 785.6,1136.22 876.71,1227.33 876.71,1479.07 v1(875.37,1480.41) 875.37,1532.7 852.85,1555.21 U3.3@823.3,1555.21 773.03,1555.21 757.35,1539.53 C127.1@753.06,1539.53
  Bottom Layer w22: v1(875.37,1480.41) U3.6@931.57,1480.41
  other v1: 517.8,1039.17 577.8,1039.17 637.8,1039.17 697.8,1039.17 517.8,1085.31 577.8,1085.31 637.8,1085.31 697.8,1085.31 517.8,1131.44
NetC127_2: C127.2 U3.1 | length 78.1
  Bottom Layer w10: C127.2@747.44,1475 817.89,1475 U3.1@823.3,1480.41
NetC129_2: C129.2 R72.2 R75.2 | length 1725.2
  Bottom Layer w10: R75.2@904.46,4343.82 955.66,4395.02 1470.66,4395.02 1577.68,4288 2093.23,4288 2180.16,4201.07 2180.16,3961.99 C129.2@2228.22,3913.93 2230.18,3915.9 R72.2@2268.28,3915.9
NetC132_1: C132.1 D3.1 R76.1 | length 191.7
  Top Layer w16: R76.1@1136.4,4608.54 C132.1@1197.38,4608.54 1203.29,4614.44 1242.97,4614.44 v1(1252.03,4605.38)
  Bottom Layer w15: D3.1@1219.98,4548.78 1252.03,4580.83 v1(1252.03,4605.38)
NetC137_1: C137.1 R81.1 U5.5 | length 209.8
  Top Layer w10: R81.1@1467.96,4594.44 C137.1@1467.96,4533.78 1488.68,4513.07 1558.96,4513.07 1566.25,4505.78 U5.5@1605.51,4505.78
NetC140_1: C140.1 L11.2 U6.3 | length 254.7
  Top Layer w30: L11.2@2504.45,2690.51 2532.54,2718.6 C140.1@2532.54,2798.66 2532.54,2885.31 U6.3@2566.66,2919.42
NetC144_1: C144.1 D4.1 R83.1 | length 157.4
  Top Layer w16: R83.1@1978.39,4608.54 C144.1@2032.19,4608.54 2053.25,4608.54 v1(2072,4589.78)
  Bottom Layer w16: D4.1@2071.85,4533.78 2071.85,4589.64 v1(2072,4589.78)
NetC154_2: C154.2 R93.2 | length 91.9
  Bottom Layer w20: R93.2@878.14,3069 914.08,3104.94 C154.2@955.17,3104.94
NetC155_2: C155.2 R94.2 | length 101.9
  Bottom Layer w20: R94.2@1561.1,3069 1597.04,3104.94 C155.2@1648.12,3104.94
NetC156_2: C156.2 R99.1 | length 87.4
  Bottom Layer w20: R99.1@1241,3358.45 1267.77,3331.68 C156.2@1267.77,3282.15
NetC157_2: C157.2 R100.1 | length 89.1
  Bottom Layer w20: R100.1@1915.45,3352.45 1953.98,3313.92 C157.2@1953.98,3279.35
NetC158_1: C158.1 C159.1 C160.1 C161.1 C162.1 C163.1 C164.1 C165.1 C166.1 C220.1 C221.1 C222.1 C223.1 C224.1 C225.1 C226.1 C227.1 D10.1 D11.1 L14.1 Q4.5 Q4.6 Q4.7 Q4.8 Q4.9@1087.83,3491.52 Q5.5 Q5.6 Q5.7 Q5.8 Q5.9@1784.32,3491.52 R99.2 R100.2 R101.1 | length 1758.3
  Top Layer w40: C224.1@810.39,3986.14 C224.1@810.88,3986.63 ; C223.1@810.88,4131.42 C224.1@810.88,3986.63 ; v1(1078.79,3939.19) 1023.04,3994.94 ; v1(1122.18,4010.6) 1111.45,4010.6 1095.78,3994.94 1023.04,3994.94 ; v1(1495.64,4007.56) 1577.84,4007.56 C225.1@1590.46,3994.94 ; 1556.35,3963.03 1495.95,3963.03 1495.95,3981.72 1496.37,3982.14 1577.67,3982.14 C225.1@1590.46,3994.94 ; C226.1@1590.46,4160.34 1590.46,4086.06 ; C222.1@1814.96,3993.68 1814.96,4070.28 ; C227.1@1814.96,4149.26 1814.96,4070.28 ; C224.1@810.88,3986.63 819.19,3994.94 1023.04,3994.94 ; C225.1@1590.46,3994.94 1590.46,4086.06 ; 1590.46,4086.06 1598.2,4078.32 1806.92,4078.32 1814.96,4070.28
  Bottom Layer w15: v1(958.58,3560.73) 965.06,3554.24 D11.1@965.06,3466.07 ; v1(1170.13,3601.34) 1231.92,3539.55 R99.2@1241,3539.55 ; v1(1651.74,3560.21) 1663.36,3548.59 D10.1@1663.36,3466.07 ; v1(1863.29,3600.82) 1915.45,3548.67 R100.2@1915.45,3533.55
  other v1: 857.48,3577.83 902.54,3577.83 1550.64,3577.31 1595.71,3577.31 1632.08,3600.82 1678.33,3600.82 1724.57,3600.82 1770.81,3600.82 1817.05,3600.82 938.92,3601.34 985.16,3601.34 1031.4,3601.34 1077.64,3601.34 1123.89,3601.34 1576.41,3614.77 883.24,3615.3 1468.38,3889.27 1312.66,3892.5 1254.44,3916.99 1496.56,3930.39 1291.4,3947.49 1467.91,3968.74 1083.67,3982.51 1332.07,3982.14 1402.76,3982.61 1247.78,3983.46 1157.21,3984.41 1436.49,4008.02 1198.55,4008.71 1291.65,4008.71 1365.8,4008.94
NetC172_2: C172.2 R103.1
NetC173_2: C173.2 R104.1
NetC174_2: C174.2 R105.1
NetC177_1: C177.1 U8.7 Y1.3 | length 298.5
  Top Layer w10: Y1.3@5967.48,4663.11 5958.95,4663.11 5936,4640.15 5936,4581.25 5959.25,4558 5988.56,4528.69 6036.31,4528.69 6048.62,4516.38 U8.7@6107.72,4516.38
NetC180_1: C180.1 R110.1 Y1.1 | length 149.5
  Top Layer w10: Y1.1@5902.52,4613.89 5898.58,4609.96 C180.1@5898.58,4558 5898.58,4532.92 5937.5,4494 R110.1@5949.31,4494
NetC181_1: C181.1 R107.1 U8.21 | length 165.4
  Top Layer w10: U8.21@6340,4490.79 6398.28,4490.79 6402.26,4486.81 R107.1@6455,4486.81 C181.1@6455,4535.59
NetC183_1: C183.1 R118.2 U8.22 | length 181.5
  Top Layer w10: v1(6285.38,4516.38) U8.22@6340,4516.38
  Bottom Layer w10: R118.2@6245.51,4406.01 C183.1@6245.51,4451.42 6245.51,4476.51 v1(6285.38,4516.38)
NetC184_1: C184.1 R118.1 | length 48
  Bottom Layer w10: C184.1@6198.27,4358.01 R118.1@6198.27,4406.01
